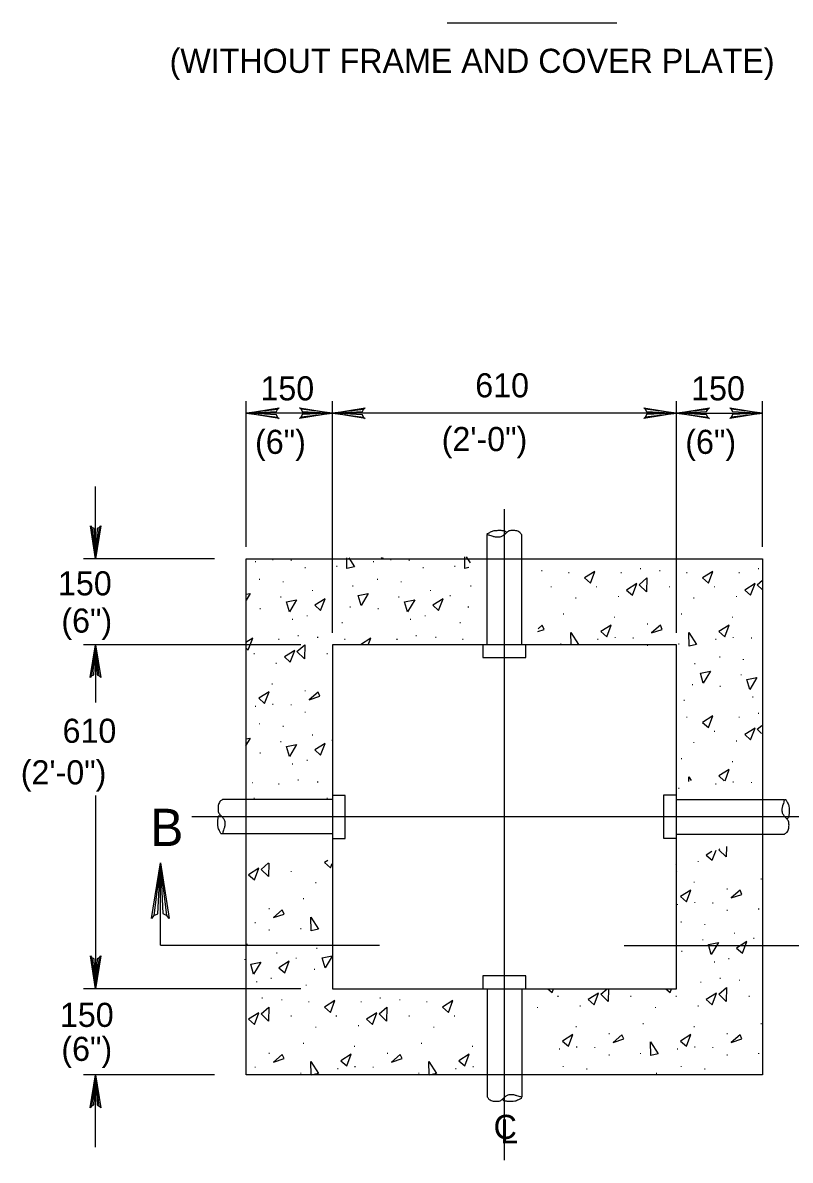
# Model space of a CAD drawing. Extents: x 638447 to 639352, y 298406 to 299000.
# Drawn here: x 638542.1 to 638649.1, y 298678.4 to 298837.1 of the extents above; entities that cross this region are included whole.
import ezdxf

# ---------------------------------------------------------------- set-up
doc = ezdxf.new("R2010")
doc.units = 0
for name, color, linetype in [('1', 7, 'Continuous'), ('2', 7, 'Continuous'), ('3', 7, 'Continuous')]:
    doc.layers.add(name, color=color, linetype=linetype)

msp = doc.modelspace()

# ---------------------------------------------------------------- linework, layer by layer
at = {"layer": '2'}
for p, q in [((638573.239125, 298764.034), (638573.239125, 298784.344)), ((638585.239125, 298752.034), (638585.239125, 298784.344)), ((638633.239125, 298752.034), (638633.239125, 298784.344)), ((638645.239125, 298764.034), (638645.239125, 298784.344)), ((638585.239125, 298782.664), (638573.239125, 298782.664)), ((638633.239125, 298782.664), (638585.239125, 298782.664)), ((638633.239125, 298782.664), (638645.239125, 298782.664)), ((638552.212375, 298762.354), (638552.212375, 298772.434)), ((638609.239125, 298678.444), (638609.239125, 298769.288)), ((638606.841125, 298762.61), (638606.841125, 298765.672)), ((638611.641125, 298762.61), (638611.641125, 298765.672)), ((638568.818375, 298762.354), (638550.532375, 298762.354)), ((638606.841125, 298750.354), (638606.841125, 298762.61)), ((638611.641125, 298750.354), (638611.641125, 298762.61)), ((638609.241125, 298750.61), (638609.241125, 298750.61)), ((638580.818375, 298750.354), (638550.532375, 298750.354)), ((638552.212375, 298750.354), (638552.212375, 298742.304)), ((638609.239125, 298750.354), (638609.239125, 298750.354)), ((638552.212375, 298729.3165), (638552.212375, 298702.354)), ((638572.983125, 298728.758), (638569.921125, 298728.758)), ((638585.239125, 298728.758), (638572.983125, 298728.758)), ((638633.239125, 298728.754), (638645.239125, 298728.754)), ((638645.239125, 298728.754), (638648.299125, 298728.754)), ((638650.717125, 298726.354), (638565.631125, 298726.354)), ((638584.983125, 298726.358), (638584.983125, 298726.358)), ((638609.239125, 298726.354), (638609.239125, 298726.354)), ((638633.239125, 298726.354), (638633.239125, 298726.354)), ((638633.239125, 298726.354), (638633.239125, 298726.354)), ((638572.983125, 298723.958), (638569.921125, 298723.958)), ((638585.239125, 298723.958), (638572.983125, 298723.958)), ((638633.239125, 298723.954), (638645.239125, 298723.954)), ((638645.239125, 298723.954), (638648.299125, 298723.954)), ((638561.268375, 298708.428), (638561.268375, 298719.9315)), ((638633.079125, 298719.638), (638633.079125, 298719.638)), ((638633.363125, 298718.786), (638633.363125, 298718.786)), ((638561.268375, 298708.428), (638591.790625, 298708.428)), ((638625.925375, 298708.386), (638661.929375, 298708.386)), ((638580.818375, 298702.354), (638550.532375, 298702.354)), ((638606.839125, 298702.354), (638606.839125, 298690.354)), ((638609.239125, 298702.354), (638609.239125, 298702.354)), ((638609.239125, 298702.354), (638609.239125, 298702.354)), ((638611.639125, 298702.354), (638611.639125, 298690.354)), ((638568.818375, 298690.354), (638550.532375, 298690.354)), ((638552.212375, 298680.274), (638552.212375, 298690.354)), ((638606.839125, 298690.354), (638606.839125, 298687.294)), ((638611.639125, 298690.354), (638611.639125, 298687.294))]:
    msp.add_line(p, q, dxfattribs=at)
for points in [[(638577.597125, 298782.118), (638577.435125, 298782.434), (638573.239125, 298782.664), (638577.597125, 298782.118), (638577.821125, 298781.926), (638573.239125, 298782.664), (638577.431125, 298782.872), (638577.585125, 298783.184), (638573.239125, 298782.664), (638577.821125, 298783.394), (638577.585125, 298783.184)], [(638580.879125, 298783.212), (638581.041125, 298782.896), (638585.239125, 298782.664), (638580.879125, 298783.212), (638580.655125, 298783.404), (638585.239125, 298782.664), (638581.045125, 298782.458), (638580.891125, 298782.146), (638585.239125, 298782.664), (638580.655125, 298781.936), (638580.891125, 298782.146)], [(638589.597125, 298782.118), (638589.435125, 298782.434), (638585.239125, 298782.664), (638589.597125, 298782.118), (638589.821125, 298781.926), (638585.239125, 298782.664), (638589.431125, 298782.872), (638589.585125, 298783.184), (638585.239125, 298782.664), (638589.821125, 298783.394), (638589.585125, 298783.184)], [(638628.879125, 298783.212), (638629.041125, 298782.896), (638633.239125, 298782.664), (638628.879125, 298783.212), (638628.655125, 298783.404), (638633.239125, 298782.664), (638629.045125, 298782.458), (638628.891125, 298782.146), (638633.239125, 298782.664), (638628.655125, 298781.936), (638628.891125, 298782.146)], [(638637.597125, 298782.118), (638637.435125, 298782.434), (638633.239125, 298782.664), (638637.597125, 298782.118), (638637.821125, 298781.926), (638633.239125, 298782.664), (638637.431125, 298782.872), (638637.585125, 298783.184), (638633.239125, 298782.664), (638637.821125, 298783.394), (638637.585125, 298783.184)], [(638640.879125, 298783.212), (638641.041125, 298782.896), (638645.239125, 298782.664), (638640.879125, 298783.212), (638640.655125, 298783.404), (638645.239125, 298782.664), (638641.045125, 298782.458), (638640.891125, 298782.146), (638645.239125, 298782.664), (638640.655125, 298781.936), (638640.891125, 298782.146)], [(638552.760375, 298766.714), (638552.444375, 298766.552), (638552.212375, 298762.354), (638552.760375, 298766.714), (638552.952375, 298766.938), (638552.212375, 298762.354), (638552.006375, 298766.548), (638551.694375, 298766.702), (638552.212375, 298762.354), (638551.484375, 298766.938), (638551.694375, 298766.702)], [(638575.713125, 298762.376), (638575.781125, 298762.314)], [(638575.781125, 298762.314), (638575.805125, 298762.376)], [(638587.265125, 298761.006), (638587.237125, 298762.472)], [(638587.513125, 298762.476), (638588.309125, 298761.246)], [(638592.023125, 298762.514), (638592.245125, 298762.314)], [(638592.245125, 298762.314), (638592.323125, 298762.516)], [(638603.729125, 298761.006), (638603.699125, 298762.612)], [(638603.887125, 298762.614), (638604.437125, 298761.766)], [(638588.309125, 298761.246), (638587.265125, 298761.006)], [(638604.287125, 298761.134), (638603.729125, 298761.006)], [(638644.495125, 298758.736), (638645.221125, 298759.368)], [(638645.215125, 298758.034), (638644.495125, 298758.736)], [(638573.777125, 298757.502), (638573.213125, 298756.568)], [(638573.217125, 298757.392), (638573.777125, 298757.502)], [(638613.907125, 298752.212), (638614.771125, 298752.496)], [(638614.519125, 298753.072), (638613.949125, 298752.582)], [(638614.771125, 298752.496), (638614.519125, 298753.072)], [(638574.125125, 298751.262), (638573.189125, 298750.676)], [(638573.501125, 298749.63), (638574.125125, 298751.262)], [(638590.589125, 298751.262), (638589.149125, 298750.362)], [(638590.243125, 298750.354), (638590.589125, 298751.262)], [(638618.523125, 298750.354), (638618.491125, 298752.076)], [(638618.491125, 298752.076), (638619.571125, 298750.408)], [(638551.666375, 298745.996), (638551.982375, 298746.158), (638552.212375, 298750.354), (638551.666375, 298745.996), (638551.474375, 298745.772), (638552.212375, 298750.354), (638552.420375, 298746.162), (638552.732375, 298746.008), (638552.212375, 298750.354), (638552.940375, 298745.772), (638552.732375, 298746.008)], [(638573.185125, 298749.912), (638573.501125, 298749.63)], [(638585.239125, 298750.354), (638585.239125, 298702.354), (638633.239125, 298702.354), (638633.239125, 298750.354), (638585.239125, 298750.354)], [(638589.149125, 298750.362), (638589.157125, 298750.354)], [(638619.571125, 298750.408), (638619.335125, 298750.354)], [(638644.495125, 298738.576), (638645.111125, 298739.112)], [(638645.105125, 298737.98), (638644.495125, 298738.576)], [(638573.777125, 298737.342), (638573.127125, 298736.266)], [(638573.131125, 298737.214), (638573.777125, 298737.342)], [(638634.965125, 298731.286), (638634.955125, 298731.916)], [(638634.955125, 298731.916), (638635.275125, 298731.422)], [(638640.595125, 298732.948), (638639.155125, 298732.048)], [(638639.155125, 298732.048), (638639.885125, 298731.392)], [(638639.997125, 298731.386), (638640.595125, 298732.948)], [(638574.125125, 298731.102), (638574.111125, 298731.092)], [(638574.125125, 298731.098), (638574.125125, 298731.102)], [(638640.209125, 298722.192), (638640.175125, 298720.758)], [(638638.181125, 298721.516), (638637.391125, 298721.022)], [(638637.391125, 298721.022), (638638.207125, 298720.29)], [(638638.207125, 298720.29), (638638.747125, 298721.706)], [(638639.143125, 298721.766), (638639.275125, 298721.882)], [(638640.175125, 298720.758), (638639.143125, 298721.766)], [(638560.342125, 298712.56625), (638560.876375, 298712.84), (638561.268375, 298719.9315), (638560.342125, 298712.56625), (638560.017625, 298712.1875), (638561.268375, 298719.9315), (638561.616375, 298712.8435), (638562.143875, 298712.5865), (638561.268375, 298719.9315), (638562.498875, 298712.1875), (638562.143875, 298712.5865)], [(638575.301125, 298719.02), (638576.335125, 298719.914)], [(638576.333125, 298718.012), (638575.301125, 298719.02)], [(638576.381125, 298719.894), (638576.333125, 298718.012)], [(638584.605125, 298720.254), (638584.145125, 298719.968)], [(638584.145125, 298719.968), (638584.961125, 298719.236)], [(638584.961125, 298719.236), (638585.191125, 298719.834)], [(638552.760375, 298706.714), (638552.444375, 298706.552), (638552.212375, 298702.354), (638552.760375, 298706.714), (638552.952375, 298706.938), (638552.212375, 298702.354), (638552.006375, 298706.548), (638551.694375, 298706.702), (638552.212375, 298702.354), (638551.484375, 298706.938), (638551.694375, 298706.702)], [(638583.833125, 298706.672), (638585.225125, 298706.944)], [(638584.229125, 298705.28), (638583.833125, 298706.672)], [(638585.225125, 298706.926), (638584.229125, 298705.28)], [(638615.281125, 298702.354), (638615.875125, 298701.822)], [(638615.875125, 298701.822), (638616.079125, 298702.354)], [(638622.679125, 298701.606), (638623.541125, 298702.354)], [(638623.711125, 298700.598), (638622.679125, 298701.606)], [(638623.755125, 298702.354), (638623.711125, 298700.598)], [(638631.745125, 298702.354), (638632.339125, 298701.822)], [(638632.339125, 298701.822), (638632.541125, 298702.354)], [(638604.329125, 298693.232), (638602.889125, 298692.332)], [(638602.889125, 298692.332), (638603.705125, 298691.6)], [(638603.705125, 298691.6), (638604.329125, 298693.232)], [(638551.666375, 298685.996), (638551.982375, 298686.158), (638552.212375, 298690.354), (638551.666375, 298685.996), (638551.474375, 298685.772), (638552.212375, 298690.354), (638552.420375, 298686.162), (638552.732375, 298686.008), (638552.212375, 298690.354), (638552.940375, 298685.772), (638552.732375, 298686.008)]]:
    msp.add_lwpolyline(points, dxfattribs=at)
for points in [[(638573.239125, 298690.354), (638573.239125, 298762.354), (638645.239125, 298762.354), (638645.239125, 298690.354)], [(638621.851125, 298760.584), (638620.411125, 298759.684), (638621.227125, 298758.952)], [(638638.315125, 298760.584), (638636.875125, 298759.684), (638637.691125, 298758.952)], [(638627.719125, 298758.892), (638626.279125, 298757.992), (638627.095125, 298757.26)], [(638628.031125, 298758.736), (638629.111125, 298759.672), (638629.063125, 298757.728)], [(638644.183125, 298758.892), (638642.743125, 298757.992), (638643.559125, 298757.26)], [(638588.837125, 298757.226), (638590.241125, 298757.502), (638589.233125, 298755.834)], [(638578.853125, 298756.338), (638580.257125, 298756.614), (638579.249125, 298754.946)], [(638584.217125, 298756.758), (638582.777125, 298755.858), (638583.593125, 298755.126)], [(638595.317125, 298756.338), (638596.721125, 298756.614), (638595.713125, 298754.946)], [(638600.681125, 298756.758), (638599.241125, 298755.858), (638600.057125, 298755.126)], [(638624.131125, 298753.108), (638622.691125, 298752.208), (638623.507125, 298751.476)], [(638631.235125, 298752.496), (638630.983125, 298753.072), (638629.747125, 298752.004)], [(638640.595125, 298753.108), (638639.155125, 298752.208), (638639.971125, 298751.476)], [(638636.035125, 298750.408), (638634.991125, 298750.168), (638634.955125, 298752.076)], [(638579.993125, 298749.57), (638578.553125, 298748.67), (638579.369125, 298747.938)], [(638580.305125, 298749.414), (638581.385125, 298750.35), (638581.337125, 298748.406)], [(638612.223125, 298750.358), (638606.223125, 298750.358), (638606.223125, 298748.558), (638612.223125, 298748.558)], [(638636.563125, 298746.388), (638637.967125, 298746.664), (638636.959125, 298744.996)], [(638643.043125, 298745.5), (638644.447125, 298745.776), (638643.439125, 298744.108)], [(638576.405125, 298743.786), (638574.965125, 298742.886), (638575.781125, 298742.154)], [(638583.509125, 298743.174), (638583.257125, 298743.75), (638582.021125, 298742.682)], [(638638.315125, 298740.424), (638636.875125, 298739.524), (638637.691125, 298738.792)], [(638644.183125, 298738.732), (638642.743125, 298737.832), (638643.559125, 298737.1)], [(638578.853125, 298736.178), (638580.257125, 298736.454), (638579.249125, 298734.786)], [(638584.217125, 298736.598), (638582.777125, 298735.698), (638583.593125, 298734.966)], [(638587.039125, 298723.338), (638587.039125, 298729.338), (638585.239125, 298729.338), (638585.239125, 298723.338)], [(638633.239125, 298723.354), (638633.239125, 298729.354), (638631.439125, 298729.354), (638631.439125, 298723.354)], [(638574.989125, 298719.176), (638573.549125, 298718.276), (638574.365125, 298717.544)], [(638635.243125, 298716.138), (638633.803125, 298715.238), (638634.619125, 298714.506)], [(638642.347125, 298715.526), (638642.095125, 298716.102), (638640.859125, 298715.034)], [(638578.505125, 298712.78), (638578.253125, 298713.356), (638577.017125, 298712.288)], [(638583.305125, 298710.692), (638582.261125, 298710.452), (638582.225125, 298712.36)], [(638637.691125, 298708.53), (638639.095125, 298708.806), (638638.087125, 298707.138)], [(638643.055125, 298708.95), (638641.615125, 298708.05), (638642.431125, 298707.318)], [(638579.213125, 298706.204), (638577.773125, 298705.304), (638578.589125, 298704.572)], [(638573.849125, 298705.784), (638575.253125, 298706.06), (638574.245125, 298704.392)], [(638612.239125, 298704.154), (638606.239125, 298704.154), (638606.239125, 298702.354), (638612.239125, 298702.354)], [(638622.367125, 298701.762), (638620.927125, 298700.862), (638621.743125, 298700.13)], [(638638.831125, 298701.762), (638637.391125, 298700.862), (638638.207125, 298700.13)], [(638639.143125, 298701.606), (638640.223125, 298702.542), (638640.175125, 298700.598)], [(638575.301125, 298698.86), (638576.381125, 298699.796), (638576.333125, 298697.852)], [(638585.585125, 298700.708), (638584.145125, 298699.808), (638584.961125, 298699.076)], [(638591.765125, 298698.86), (638592.845125, 298699.796), (638592.797125, 298697.852)], [(638602.049125, 298700.708), (638600.609125, 298699.808), (638601.425125, 298699.076)], [(638574.989125, 298699.016), (638573.549125, 298698.116), (638574.365125, 298697.384)], [(638591.453125, 298699.016), (638590.013125, 298698.116), (638590.829125, 298697.384)], [(638618.779125, 298695.978), (638617.339125, 298695.078), (638618.155125, 298694.346)], [(638625.883125, 298695.366), (638625.631125, 298695.942), (638624.395125, 298694.874)], [(638635.243125, 298695.978), (638633.803125, 298695.078), (638634.619125, 298694.346)], [(638642.347125, 298695.366), (638642.095125, 298695.942), (638640.859125, 298694.874)], [(638630.683125, 298693.278), (638629.639125, 298693.038), (638629.603125, 298694.946)], [(638578.505125, 298692.62), (638578.253125, 298693.196), (638577.017125, 298692.128)], [(638583.305125, 298690.532), (638582.261125, 298690.292), (638582.225125, 298692.2)], [(638587.865125, 298693.232), (638586.425125, 298692.332), (638587.241125, 298691.6)], [(638594.969125, 298692.62), (638594.717125, 298693.196), (638593.481125, 298692.128)], [(638599.769125, 298690.532), (638598.725125, 298690.292), (638598.689125, 298692.2)]]:
    msp.add_lwpolyline(points, close=True, dxfattribs=at)
for points in [[(638606.841125, 298765.846), (638606.907125, 298765.89), (638607.113125, 298765.988), (638607.285125, 298766.084), (638607.557125, 298766.214), (638607.805125, 298766.29), (638608.217125, 298766.312), (638608.497125, 298766.322), (638608.735125, 298766.322), (638608.973125, 298766.29), (638609.245125, 298766.258), (638609.395125, 298766.16), (638609.559125, 298766.02)], [(638611.641125, 298765.672), (638611.365125, 298766.03), (638610.825125, 298766.258), (638610.251125, 298766.29), (638609.741125, 298766.172), (638609.385125, 298765.858), (638609.103125, 298765.62), (638608.715125, 298765.402), (638608.205125, 298765.348), (638607.967125, 298765.37), (638607.545125, 298765.49), (638607.221125, 298765.598), (638606.853125, 298765.75), (638606.841125, 298765.846)], [(638569.921125, 298728.758), (638569.563125, 298728.482), (638569.335125, 298727.94), (638569.303125, 298727.368), (638569.421125, 298726.858), (638569.735125, 298726.502), (638569.973125, 298726.22), (638570.191125, 298725.83), (638570.245125, 298725.322), (638570.223125, 298725.084), (638570.103125, 298724.662), (638569.995125, 298724.338), (638569.843125, 298723.97), (638569.747125, 298723.958)], [(638648.299125, 298723.954), (638648.659125, 298724.23), (638648.887125, 298724.772), (638648.919125, 298725.344), (638648.801125, 298725.854), (638648.487125, 298726.21), (638648.249125, 298726.492), (638648.031125, 298726.882), (638647.977125, 298727.39), (638647.999125, 298727.628), (638648.119125, 298728.05), (638648.227125, 298728.376), (638648.377125, 298728.744), (638648.475125, 298728.754)], [(638648.475125, 298728.754), (638648.519125, 298728.688), (638648.615125, 298728.484), (638648.713125, 298728.31), (638648.843125, 298728.04), (638648.919125, 298727.79), (638648.941125, 298727.38), (638648.951125, 298727.098), (638648.951125, 298726.86), (638648.919125, 298726.622), (638648.887125, 298726.352), (638648.789125, 298726.2), (638648.649125, 298726.038)], [(638569.747125, 298723.958), (638569.703125, 298724.024), (638569.605125, 298724.228), (638569.509125, 298724.402), (638569.379125, 298724.672), (638569.303125, 298724.922), (638569.281125, 298725.332), (638569.271125, 298725.614), (638569.271125, 298725.852), (638569.303125, 298726.09), (638569.335125, 298726.36), (638569.433125, 298726.512), (638569.573125, 298726.674)], [(638606.839125, 298687.294), (638607.113125, 298686.934), (638607.655125, 298686.706), (638608.229125, 298686.674), (638608.737125, 298686.794), (638609.095125, 298687.106), (638609.375125, 298687.346), (638609.765125, 298687.562), (638610.273125, 298687.616), (638610.511125, 298687.594), (638610.933125, 298687.474), (638611.259125, 298687.366), (638611.627125, 298687.216), (638611.639125, 298687.118)], [(638611.639125, 298687.118), (638611.573125, 298687.074), (638611.367125, 298686.978), (638611.193125, 298686.88), (638610.923125, 298686.75), (638610.675125, 298686.674), (638610.263125, 298686.652), (638609.981125, 298686.642), (638609.743125, 298686.642), (638609.505125, 298686.674), (638609.235125, 298686.706), (638609.083125, 298686.804), (638608.921125, 298686.944)]]:
    msp.add_spline(points, degree=3, dxfattribs=at)
at = {"layer": '3'}
msp.add_line((638601.258875, 298837.12175), (638624.929125, 298837.12175), dxfattribs=at)

# ---------------------------------------------------------------- texts
at = {"layer": '1'}
for s, p in [('(2\'-0")', (638600.483875, 298777.37)), ('(6")', (638574.456625, 298776.98125)), ('(6")', (638634.458375, 298776.98125)), ('(6")', (638547.442875, 298752.0455)), ('(2\'-0")', (638541.780875, 298730.875)), ('(6")', (638547.442875, 298692.3035))]:
    msp.add_text(s, height=3.36, dxfattribs=at).set_placement(p)
at = {"layer": '2'}
for p in [(638574.317125, 298761.846), (638576.729125, 298762.122), (638579.273125, 298762.05), (638590.781125, 298761.846), (638593.193125, 298762.122), (638595.737125, 298762.05), (638581.241125, 298761.018), (638585.645125, 298761.222), (638597.705125, 298761.018), (638602.109125, 298761.222), (638614.243125, 298760.608), (638618.011125, 298760.332), (638625.307125, 298760.332), (638627.983125, 298760.872), (638630.707125, 298760.608), (638634.475125, 298760.332), (638641.771125, 298760.332), (638644.447125, 298760.872), (638574.857125, 298759.398), (638578.157125, 298759.05), (638587.865125, 298758.462), (638591.321125, 298759.398), (638594.621125, 298759.05), (638604.329125, 298758.462), (638615.563125, 298758.352), (638621.851125, 298758.352), (638632.027125, 298758.352), (638638.315125, 298758.352), (638577.845125, 298756.914), (638577.845125, 298756.914), (638582.273125, 298757.838), (638584.985125, 298757.106), (638594.309125, 298756.914), (638594.309125, 298756.914), (638598.737125, 298757.838), (638601.449125, 298757.106), (638618.983125, 298756.792), (638624.923125, 298756.996), (638635.447125, 298756.792), (638641.387125, 298756.996), (638574.941125, 298755.318), (638587.529125, 298755.546), (638591.405125, 298755.318), (638603.993125, 298755.546), (638579.477125, 298753.806), (638581.505125, 298754.298), (638595.941125, 298753.806), (638597.969125, 298754.298), (638617.267125, 298754.548), (638624.371125, 298754.116), (638633.731125, 298754.548), (638640.835125, 298754.116), (638586.389125, 298753.338), (638602.853125, 298753.338), (638628.967125, 298753.156), (638577.581125, 298751.01), (638580.257125, 298751.55), (638582.981125, 298751.286), (638586.749125, 298751.01), (638594.045125, 298751.01), (638596.721125, 298751.55), (638599.445125, 298751.286), (638603.213125, 298751.01), (638616.907125, 298750.384), (638622.043125, 298751.008), (638624.455125, 298751.284), (638626.999125, 298751.212), (638633.371125, 298750.384), (638638.507125, 298751.008), (638640.919125, 298751.284), (638643.463125, 298751.212), (638574.125125, 298749.03), (638584.301125, 298749.03), (638628.967125, 298750.18), (638577.197125, 298747.674), (638635.591125, 298747.624), (638639.047125, 298748.56), (638642.347125, 298748.212), (638642.035125, 298746.076), (638642.035125, 298746.076), (638576.645125, 298744.794), (638635.255125, 298744.708), (638639.131125, 298744.48), (638581.241125, 298743.834), (638634.115125, 298742.5), (638643.667125, 298742.968), (638574.317125, 298741.686), (638576.729125, 298741.962), (638579.273125, 298741.89), (638581.241125, 298740.858), (638634.475125, 298740.172), (638641.771125, 298740.172), (638644.447125, 298740.712), (638574.857125, 298739.238), (638578.157125, 298738.89), (638582.273125, 298737.678), (638638.315125, 298738.192), (638577.845125, 298736.754), (638577.845125, 298736.754), (638584.985125, 298736.946), (638635.447125, 298736.632), (638641.387125, 298736.836), (638574.941125, 298735.158), (638579.477125, 298733.646), (638581.505125, 298734.138), (638633.731125, 298734.388), (638640.835125, 298733.956), (638580.257125, 298731.39), (638577.581125, 298730.85), (638582.981125, 298731.126), (638633.371125, 298730.224), (638638.507125, 298730.848), (638640.919125, 298731.124), (638643.463125, 298731.052), (638574.125125, 298728.87), (638584.301125, 298728.87), (638579.297125, 298718.636), (638636.035125, 298720.026), (638582.717125, 298717.076), (638635.483125, 298717.146), (638644.843125, 298717.578), (638640.079125, 298716.186), (638581.001125, 298714.832), (638633.155125, 298714.038), (638635.567125, 298714.314), (638638.111125, 298714.242), (638576.237125, 298713.44), (638640.079125, 298713.21), (638644.483125, 298713.414), (638574.269125, 298711.496), (638633.695125, 298711.59), (638636.995125, 298711.242), (638576.237125, 298710.464), (638580.641125, 298710.668), (638636.683125, 298709.106), (638636.683125, 298709.106), (638641.111125, 298710.03), (638643.823125, 298709.298), (638573.153125, 298708.496), (638582.861125, 298707.908), (638572.841125, 298706.36), (638577.269125, 298707.284), (638579.981125, 298706.552), (638633.779125, 298707.51), (638638.315125, 298705.998), (638640.343125, 298706.49), (638582.525125, 298704.992), (638574.473125, 298703.252), (638576.501125, 298703.744), (638581.385125, 298702.784), (638636.419125, 298703.202), (638639.095125, 298703.742), (638641.819125, 298703.478), (638616.499125, 298701.222), (638626.675125, 298701.222), (638632.963125, 298701.222), (638643.139125, 298701.222), (638575.253125, 298700.996), (638577.977125, 298700.732), (638581.745125, 298700.456), (638589.041125, 298700.456), (638591.717125, 298700.996), (638594.441125, 298700.732), (638598.209125, 298700.456), (638613.631125, 298699.662), (638619.571125, 298699.866), (638630.095125, 298699.662), (638636.035125, 298699.866), (638579.297125, 298698.476), (638585.585125, 298698.476), (638595.761125, 298698.476), (638602.049125, 298698.476), (638582.717125, 298696.916), (638588.657125, 298697.12), (638599.181125, 298696.916), (638619.019125, 298696.986), (638628.379125, 298697.418), (638635.483125, 298696.986), (638644.843125, 298697.418), (638623.615125, 298696.026), (638640.079125, 298696.026), (638576.237125, 298693.28), (638581.001125, 298694.672), (638588.105125, 298694.24), (638592.701125, 298693.28), (638597.465125, 298694.672), (638604.569125, 298694.24), (638616.691125, 298693.878), (638619.103125, 298694.154), (638621.647125, 298694.082), (638628.019125, 298693.254), (638633.155125, 298693.878), (638635.567125, 298694.154), (638638.111125, 298694.082), (638644.483125, 298693.254), (638623.615125, 298693.05), (638640.079125, 298693.05), (638574.269125, 298691.336), (638576.237125, 298690.304), (638580.641125, 298690.508), (638585.777125, 298691.132), (638588.189125, 298691.408), (638590.733125, 298691.336), (638592.701125, 298690.304), (638597.105125, 298690.508), (638602.241125, 298691.132), (638604.653125, 298691.408), (638617.231125, 298691.43), (638620.531125, 298691.082), (638630.239125, 298690.494), (638633.695125, 298691.43), (638636.995125, 298691.082)]:
    msp.add_text('.', height=1.116, dxfattribs=at).set_placement(p)
at = {"layer": '3'}
for s, height, p in [('(WITHOUT FRAME AND COVER PLATE)', 3.359988, (638562.538375, 298830.13375)), ('150', 3.36, (638575.204875, 298784.444)), ('610', 3.36, (638605.167375, 298784.868)), ('150', 3.36, (638635.270875, 298784.444)), ('150', 3.36, (638546.975125, 298757.2435)), ('610', 3.36, (638547.612875, 298736.67625)), ('B', 5.2, (638559.824625, 298722.276)), ('150', 3.36, (638547.244875, 298697.046)), ('C', 3.359988, (638607.723125, 298681.42)), ('L', 3.359988, (638608.647125, 298680.796))]:
    msp.add_text(s, height=height, dxfattribs=at).set_placement(p)

doc.saveas('drawing.dxf')
